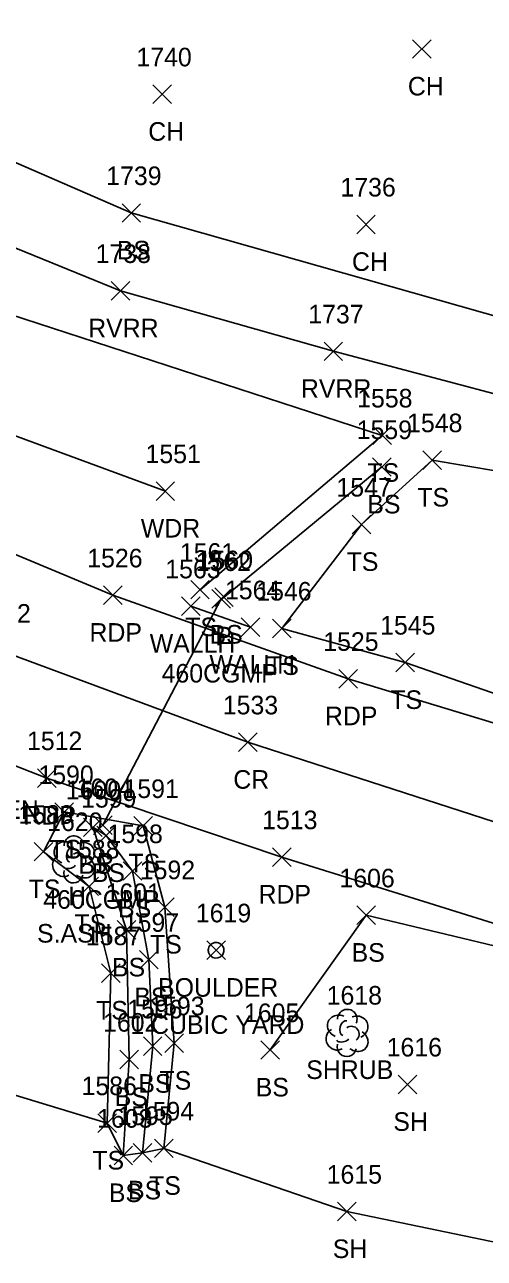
# Model space of a CAD drawing. Extents: x 1616726 to 1619875, y 273782 to 276557.
# Drawn here: x 1616834 to 1616883.5, y 276165.6 to 276298.3 of the extents above; entities that cross this region are included whole.
import ezdxf

# ---------------------------------------------------------------- set-up
doc = ezdxf.new("R2010")
doc.units = 0
for name, color, linetype in [('D_A', 7, 'Continuous'), ('D_C', 7, 'Continuous'), ('D_I', 7, 'Continuous'), ('D_TIC', 7, 'Continuous'), ('DCP', 7, 'Continuous'), ('DHW', 7, 'Continuous'), ('L_A', 7, 'Continuous'), ('L_C', 7, 'Continuous'), ('L_I', 7, 'Continuous'), ('L_TIC', 7, 'Continuous'), ('LAWA', 7, 'Continuous'), ('LAWE', 7, 'Continuous'), ('LELB', 7, 'Continuous'), ('Level 45', 7, 'Continuous'), ('LSH', 7, 'Continuous'), ('LSOGP', 7, 'Continuous'), ('LTD', 7, 'Continuous'), ('P_A', 7, 'Continuous'), ('P_I', 7, 'Continuous'), ('P_TIC', 7, 'Continuous'), ('PET', 7, 'Continuous'), ('PRC', 7, 'Continuous')]:
    doc.layers.add(name, color=color, linetype=linetype)

msp = doc.modelspace()

# ---------------------------------------------------------------- linework, layer by layer
at = {"layer": 'D_TIC'}
for points in [[(1616850.89, 276234.79), (1616852.89, 276236.79)], [(1616852.89, 276234.79), (1616850.89, 276236.79)], [(1616854.16, 276235.58), (1616856.16, 276237.58)], [(1616856.16, 276235.58), (1616854.16, 276237.58)], [(1616857.31, 276232.54), (1616859.31, 276234.54)], [(1616859.31, 276232.54), (1616857.31, 276234.54)], [(1616841.43, 276211.25), (1616843.43, 276213.25)], [(1616843.43, 276211.25), (1616841.43, 276213.25)]]:
    msp.add_lwpolyline(points, dxfattribs=at)
at = {"layer": 'DCP'}
msp.add_lwpolyline([(1616855.16, 276236.58), (1616842.43, 276212.25)], dxfattribs=at)
at = {"layer": 'DHW'}
msp.add_lwpolyline([(1616851.89, 276235.79), (1616858.31, 276233.54)], dxfattribs=at)
at = {"layer": 'L_TIC'}
for points in [[(1616875.75, 276294.73), (1616877.75, 276296.73)], [(1616877.75, 276294.73), (1616875.75, 276296.73)], [(1616847.83, 276289.86), (1616849.83, 276291.86)], [(1616849.83, 276289.86), (1616847.83, 276291.86)], [(1616844.5, 276277.09), (1616846.5, 276279.09)], [(1616846.5, 276277.09), (1616844.5, 276279.09)], [(1616869.74, 276275.86), (1616871.74, 276277.86)], [(1616871.74, 276275.86), (1616869.74, 276277.86)], [(1616843.35, 276268.71), (1616845.35, 276270.71)], [(1616845.35, 276268.71), (1616843.35, 276270.71)], [(1616866.23, 276262.21), (1616868.23, 276264.21)], [(1616868.23, 276262.21), (1616866.23, 276264.21)], [(1616871.48, 276253.17), (1616873.48, 276255.17)], [(1616873.48, 276253.17), (1616871.48, 276255.17)], [(1616876.85, 276250.51), (1616878.85, 276252.51)], [(1616878.85, 276250.51), (1616876.85, 276252.51)], [(1616871.44, 276249.77), (1616873.44, 276251.77)], [(1616873.44, 276249.77), (1616871.44, 276251.77)], [(1616848.16, 276247.18), (1616850.16, 276249.18)], [(1616850.16, 276247.18), (1616848.16, 276249.18)], [(1616869.25, 276243.59), (1616871.25, 276245.59)], [(1616871.25, 276243.59), (1616869.25, 276245.59)], [(1616851.89, 276236.57), (1616853.89, 276238.57)], [(1616853.89, 276236.57), (1616851.89, 276238.57)], [(1616854.47, 276235.77), (1616856.47, 276237.77)], [(1616856.47, 276235.77), (1616854.47, 276237.77)], [(1616860.69, 276232.4), (1616862.69, 276234.4)], [(1616862.69, 276232.4), (1616860.69, 276234.4)], [(1616873.95, 276228.74), (1616875.95, 276230.74)], [(1616875.95, 276228.74), (1616873.95, 276230.74)], [(1616837.28, 276212.66), (1616839.28, 276214.66)], [(1616839.28, 276212.66), (1616837.28, 276214.66)], [(1616840.37, 276211.01), (1616842.37, 276213.01)], [(1616842.37, 276211.01), (1616840.37, 276213.01)], [(1616845.78, 276211.16), (1616847.78, 276213.16)], [(1616847.78, 276211.16), (1616845.78, 276213.16)], [(1616841.8, 276210.13), (1616843.8, 276212.13)], [(1616843.8, 276210.13), (1616841.8, 276212.13)], [(1616835.05, 276208.39), (1616837.05, 276210.39)], [(1616837.05, 276208.39), (1616835.05, 276210.39)], [(1616844.63, 276206.31), (1616846.63, 276208.31)], [(1616846.63, 276206.31), (1616844.63, 276208.31)], [(1616839.98, 276204.66), (1616841.98, 276206.66)], [(1616841.98, 276204.66), (1616839.98, 276206.66)], [(1616848.1, 276202.43), (1616850.1, 276204.43)], [(1616850.1, 276202.43), (1616848.1, 276204.43)], [(1616869.75, 276201.55), (1616871.75, 276203.55)], [(1616871.75, 276201.55), (1616869.75, 276203.55)], [(1616843.98, 276199.97), (1616845.98, 276201.97)], [(1616845.98, 276199.97), (1616843.98, 276201.97)], [(1616853.62, 276197.79), (1616855.62, 276199.79)], [(1616855.62, 276197.79), (1616853.62, 276199.79)], [(1616846.38, 276196.77), (1616848.38, 276198.77)], [(1616848.38, 276196.77), (1616846.38, 276198.77)], [(1616842.3, 276195.33), (1616844.3, 276197.33)], [(1616844.3, 276195.33), (1616842.3, 276197.33)], [(1616846.8, 276187.46), (1616848.8, 276189.46)], [(1616848.8, 276187.46), (1616846.8, 276189.46)], [(1616849.12, 276187.79), (1616851.12, 276189.79)], [(1616851.12, 276187.79), (1616849.12, 276189.79)], [(1616859.43, 276187.06), (1616861.43, 276189.06)], [(1616861.43, 276187.06), (1616859.43, 276189.06)], [(1616844.27, 276186.03), (1616846.27, 276188.03)], [(1616846.27, 276186.03), (1616844.27, 276188.03)], [(1616874.19, 276183.36), (1616876.19, 276185.36)], [(1616876.19, 276183.36), (1616874.19, 276185.36)], [(1616841.9, 276179.2), (1616843.9, 276181.2)], [(1616843.9, 276179.2), (1616841.9, 276181.2)], [(1616848.01, 276176.48), (1616850.01, 276178.48)], [(1616850.01, 276176.48), (1616848.01, 276178.48)], [(1616843.64, 276175.7), (1616845.64, 276177.7)], [(1616845.64, 276175.7), (1616843.64, 276177.7)], [(1616845.71, 276175.99), (1616847.71, 276177.99)], [(1616847.71, 276175.99), (1616845.71, 276177.99)], [(1616867.68, 276169.68), (1616869.68, 276171.68)], [(1616869.68, 276169.68), (1616867.68, 276171.68)]]:
    msp.add_lwpolyline(points, dxfattribs=at)
at = {"layer": 'LAWA'}
msp.add_lwpolyline([(1616849.16, 276248.18), (1616818.87, 276259.31), (1616781.79, 276275.58)], dxfattribs=at)
at = {"layer": 'LAWE'}
msp.add_lwpolyline([(1617025.7, 276233.23), (1617015.62, 276235.97), (1617001.8, 276236.48), (1616993.71, 276237.76), (1616982.58, 276237.2), (1616969.98, 276238.82), (1616958.41, 276240.14), (1616941.63, 276245.84), (1616918.28, 276250.86), (1616897.52, 276255.18), (1616867.23, 276263.21), (1616844.35, 276269.71), (1616814.42, 276281.91), (1616791.45, 276293.2)], dxfattribs=at)
at = {"layer": 'LELB'}
for points in [[(1617180.33, 276288.33), (1617161.43, 276281.85), (1617137.1, 276278.45), (1617120.41, 276268.03), (1617108.3, 276262.95), (1617094.24, 276258.02), (1617079.48, 276248.1), (1617068.22, 276247.78), (1617049.15, 276245.5), (1617035.06, 276240.81), (1617026.01, 276236.23), (1617014.97, 276241.9), (1616972.47, 276247.82), (1616960.61, 276245.77), (1616944.03, 276250.47), (1616920.65, 276257.27), (1616898.69, 276263.02), (1616845.5, 276278.09), (1616816.83, 276290.56), (1616792.38, 276296.23)], [(1616787.97, 276286.47), (1616805.45, 276276.63), (1616830.82, 276267.71), (1616872.48, 276254.17), (1616852.89, 276237.57)], [(1616930.41, 276218.6), (1616913.38, 276221.93), (1616895.08, 276222.74), (1616874.95, 276229.74), (1616861.69, 276233.4), (1616870.25, 276244.59), (1616877.85, 276251.51), (1616899.15, 276247.91), (1616918.01, 276240.69)], [(1616872.44, 276250.77), (1616855.47, 276236.77)], [(1616842.9, 276180.2), (1616843.3, 276196.33), (1616840.98, 276205.66), (1616836.05, 276209.39), (1616838.28, 276213.66), (1616846.78, 276212.16), (1616849.1, 276203.43), (1616850.12, 276188.79), (1616849.01, 276177.48)], [(1616846.71, 276176.99), (1616847.8, 276188.46), (1616847.38, 276197.77), (1616845.63, 276207.31), (1616842.8, 276211.13), (1616841.37, 276212.01), (1616844.98, 276200.97), (1616845.27, 276187.03), (1616844.64, 276176.7)], [(1616860.43, 276188.06), (1616870.75, 276202.55), (1616889.75, 276198.01), (1616902.37, 276195.47)]]:
    msp.add_lwpolyline(points, dxfattribs=at)
at = {"layer": 'Level 45'}
msp.add_lwpolyline([(1616853.78, 276198.83), (1616853.78, 276198.75), (1616853.79, 276198.65), (1616853.81, 276198.56), (1616853.84, 276198.49), (1616853.87, 276198.42), (1616853.89, 276198.36), (1616853.93, 276198.3), (1616853.99, 276198.23), (1616854.04, 276198.18), (1616854.12, 276198.11), (1616854.27, 276198.02), (1616854.4, 276197.97), (1616854.58, 276197.94), (1616854.79, 276197.96), (1616854.92, 276198), (1616855.03, 276198.05), (1616855.13, 276198.11), (1616855.21, 276198.18), (1616855.26, 276198.24), (1616855.33, 276198.32), (1616855.39, 276198.44), (1616855.43, 276198.54), (1616855.46, 276198.67), (1616855.46, 276198.82), (1616855.44, 276198.99), (1616855.41, 276199.09), (1616855.36, 276199.19), (1616855.28, 276199.32), (1616855.18, 276199.42), (1616855.01, 276199.53), (1616854.87, 276199.59), (1616854.72, 276199.62), (1616854.6, 276199.63), (1616854.46, 276199.62), (1616854.29, 276199.56), (1616854.19, 276199.51), (1616854.07, 276199.42), (1616853.94, 276199.29), (1616853.89, 276199.2), (1616853.85, 276199.11), (1616853.8, 276198.99), (1616853.79, 276198.93)], close=True, dxfattribs=at)
at = {"layer": 'LSH'}
msp.add_line((1616868.68, 276189.94), (1616868.68, 276189.94), dxfattribs=at)
msp.add_line((1616868.68, 276189.94), (1616868.68, 276189.94), dxfattribs=at)
msp.add_arc((1616868.73, 276191.38), 1.05, 335.5272, 180.9563, dxfattribs=at)
for centre, major_axis, ratio, start_param, end_param in [((1616867.89, 276190.61), (1.21, -0.51), 0.895232, 1.570796, 4.712389), ((1616869.72, 276190.53), (-1.14, -0.48), 0.949671, 1.570796, 4.712389), ((1616867.6, 276189.23), (0.58, -1.04), 0.959034, 3.141593, 6.283185), ((1616868.47, 276190.4), (-0.208, -0.792), 0.645439, 3.141593, 6.283185), ((1616869.18, 276189.78), (-0.5, 0.667), 0.989748, 3.141593, 6.283185), ((1616868.22, 276189.19), (-0.625, -0.083), 0.423636, 0, 3.141593), ((1616869.68, 276189.11), (-1.09, 0.79), 0.841452, 1.570796, 4.712389), ((1616868.68, 276188.44), (0.26, 1.06), 0.942809, 1.570796, 4.712389)]:
    msp.add_ellipse(centre, major_axis=major_axis, ratio=ratio, start_param=start_param, end_param=end_param, dxfattribs=at)
at = {"layer": 'LSOGP'}
msp.add_lwpolyline([(1616793.68, 276308.95), (1616792.38, 276296.23), (1616791.45, 276293.2), (1616787.97, 276286.47), (1616782.93, 276276.29), (1616781.79, 276275.58), (1616777.93, 276266.16), (1616773.7, 276256.44), (1616769.24, 276246.91), (1616756.89, 276246.26), (1616747.56, 276224.4), (1616766.56, 276216.64), (1616771.16, 276212.03), (1616782.84, 276206.49), (1616798.63, 276193.86), (1616823.2, 276186.17), (1616842.9, 276180.2), (1616844.64, 276176.7), (1616846.71, 276176.99), (1616849.01, 276177.48), (1616868.68, 276170.68), (1616889.93, 276166.26)], dxfattribs=at)
at = {"layer": 'LTD'}
msp.add_line((1616839.28, 276208.61), (1616839.28, 276208.61), dxfattribs=at)
msp.add_line((1616839.28, 276208.61), (1616839.28, 276208.61), dxfattribs=at)
msp.add_arc((1616839.32, 276210.04), 1.05, 335.5272, 180.9563, dxfattribs=at)
for centre, major_axis, ratio, start_param, end_param in [((1616838.49, 276209.27), (1.21, -0.51), 0.895232, 1.570796, 4.712389), ((1616840.32, 276209.19), (-1.14, -0.48), 0.949671, 1.570796, 4.712389), ((1616838.19, 276207.9), (0.58, -1.04), 0.959034, 3.141593, 6.283185), ((1616839.07, 276209.07), (-0.208, -0.792), 0.645439, 3.141593, 6.283185), ((1616839.78, 276208.44), (-0.5, 0.667), 0.989748, 3.141593, 6.283185), ((1616840.28, 276207.77), (-1.09, 0.79), 0.841452, 1.570796, 4.712389), ((1616839.28, 276207.11), (0.26, 1.06), 0.942809, 1.570796, 4.712389), ((1616838.82, 276207.86), (-0.625, -0.083), 0.423636, 0, 3.141593)]:
    msp.add_ellipse(centre, major_axis=major_axis, ratio=ratio, start_param=start_param, end_param=end_param, dxfattribs=at)
at = {"layer": 'P_TIC'}
for points in [[(1616842.51, 276235.97), (1616844.51, 276237.97)], [(1616844.51, 276235.97), (1616842.51, 276237.97)], [(1616867.83, 276226.99), (1616869.83, 276228.99)], [(1616869.83, 276226.99), (1616867.83, 276228.99)], [(1616857.04, 276220.16), (1616859.04, 276222.16)], [(1616859.04, 276220.16), (1616857.04, 276222.16)], [(1616835.41, 276216.31), (1616837.41, 276218.31)], [(1616837.41, 276216.31), (1616835.41, 276218.31)], [(1616860.69, 276207.81), (1616862.69, 276209.81)], [(1616862.69, 276207.81), (1616860.69, 276209.81)]]:
    msp.add_lwpolyline(points, dxfattribs=at)
at = {"layer": 'PET'}
for points in [[(1616988.41, 276201.28), (1616954.9, 276207.04), (1616922.49, 276213.04), (1616897.19, 276219.39), (1616868.83, 276227.99), (1616843.51, 276236.97), (1616821.5, 276246.17), (1616797.48, 276256.89), (1616777.93, 276266.16)], [(1616769.24, 276246.91), (1616790.9, 276236.62), (1616808.6, 276228.19), (1616836.41, 276217.31), (1616861.69, 276208.81), (1616891.18, 276199.57), (1616916.28, 276193.27), (1616944.97, 276187.68), (1616979.27, 276181.76), (1617009.13, 276177.18), (1617040.1, 276173.73), (1617058.02, 276171.48)]]:
    msp.add_lwpolyline(points, dxfattribs=at)
at = {"layer": 'PRC'}
msp.add_lwpolyline([(1616773.7, 276256.44), (1616798, 276244.91), (1616831.43, 276231.02), (1616858.04, 276221.16), (1616889.3, 276211.07), (1616917.92, 276203.82), (1616952.65, 276196.97), (1616987.1, 276190.69)], dxfattribs=at)

# ---------------------------------------------------------------- texts
at = {"layer": 'D_A'}
for s, p in [('WALLH', (1616847.48, 276230.79)), ('P', (1616854.54, 276231.58)), ('WALLH', (1616853.9, 276228.54)), ('P', (1616841.81, 276207.25))]:
    msp.add_text(s, height=2, dxfattribs=at).set_placement(p)
at = {"layer": 'D_C'}
for p in [(1616848.76, 276227.58), (1616836.03, 276203.25)]:
    msp.add_text('460CGMP', height=2, dxfattribs=at).set_placement(p)
at = {"layer": 'D_I'}
for s, p in [('1563', (1616849.15, 276238.79)), ('1562', (1616852.42, 276239.58)), ('1564', (1616855.57, 276236.54)), ('1604', (1616839.61, 276215.25))]:
    msp.add_text(s, height=2, dxfattribs=at).set_placement(p)
at = {"layer": 'L_A'}
for s, p in [('CH', (1616875.24, 276290.73)), ('CH', (1616847.32, 276285.86)), ('BS', (1616843.94, 276273.09)), ('CH', (1616869.23, 276271.86)), ('RVRR', (1616840.86, 276264.71)), ('RVRR', (1616863.74, 276258.21)), ('TS', (1616870.89, 276249.17)), ('TS', (1616876.26, 276246.51)), ('BS', (1616870.88, 276245.77)), ('WDR', (1616846.52, 276243.18)), ('TS', (1616868.66, 276239.59)), ('TS', (1616851.3, 276232.57)), ('BS', (1616853.91, 276231.77)), ('TS', (1616860.1, 276228.4)), ('TS', (1616873.36, 276224.74)), ('GARDEN', (1616824.11, 276212.92)), ('TS', (1616836.69, 276208.66)), ('BS', (1616839.81, 276207.01)), ('TS', (1616845.19, 276207.16)), ('BS', (1616841.24, 276206.13)), ('TS', (1616834.46, 276204.39)), ('H', (1616838.71, 276203.61)), ('BS', (1616844.07, 276202.31)), ('TS', (1616839.39, 276200.66)), ('TS', (1616847.51, 276198.43)), ('BS', (1616869.19, 276197.55)), ('BS', (1616843.42, 276195.97)), ('BOULDER', (1616848.38, 276193.79)), ('BS', (1616845.82, 276192.77)), ('TS', (1616841.71, 276191.33)), ('SHRUB', (1616864.31, 276184.94)), ('BS', (1616846.25, 276183.46)), ('TS', (1616848.53, 276183.79)), ('BS', (1616858.88, 276183.06)), ('BS', (1616843.72, 276182.03)), ('SH', (1616873.68, 276179.36)), ('TS', (1616841.31, 276175.2)), ('TS', (1616847.41, 276172.48)), ('BS', (1616843.08, 276171.7)), ('BS', (1616845.15, 276171.99)), ('SH', (1616867.17, 276165.68))]:
    msp.add_text(s, height=2, dxfattribs=at).set_placement(p)
at = {"layer": 'L_C'}
for s, p in [('S.ASH', (1616835.36, 276199.61)), ('1 CUBIC YARD', (1616845.39, 276189.79))]:
    msp.add_text(s, height=2, dxfattribs=at).set_placement(p)
at = {"layer": 'L_I'}
for s, p in [('1740', (1616846.05, 276293.86)), ('1739', (1616842.8, 276281.09)), ('1736', (1616867.99, 276279.86)), ('1738', (1616841.66, 276272.71)), ('1737', (1616864.53, 276266.21)), ('1558', (1616869.79, 276257.17)), ('1548', (1616875.16, 276254.51)), ('1559', (1616869.74, 276253.77)), ('1551', (1616847.03, 276251.18)), ('1547', (1616867.56, 276247.59)), ('1561', (1616850.72, 276240.57)), ('1560', (1616852.64, 276239.77)), ('1546', (1616858.94, 276236.4)), ('1545', (1616872.26, 276232.74)), ('1590', (1616835.51, 276216.66)), ('1600', (1616838.46, 276215.01)), ('1591', (1616844.66, 276215.16)), ('1599', (1616840.1, 276214.13)), ('1589', (1616833.35, 276212.39)), ('1620', (1616836.45, 276211.61)), ('1598', (1616842.94, 276210.31)), ('1588', (1616838.28, 276208.66)), ('1592', (1616846.41, 276206.43)), ('1606', (1616867.88, 276205.55)), ('1601', (1616842.73, 276203.97)), ('1619', (1616852.44, 276201.79)), ('1597', (1616844.69, 276200.77)), ('1587', (1616840.61, 276199.33)), ('1618', (1616866.51, 276192.94)), ('1596', (1616845.06, 276191.46)), ('1593', (1616847.43, 276191.79)), ('1605', (1616857.62, 276191.06)), ('1602', (1616842.46, 276190.03)), ('1616', (1616872.96, 276187.36)), ('1586', (1616840.15, 276183.2)), ('1594', (1616846.31, 276180.48)), ('1603', (1616841.82, 276179.7)), ('1595', (1616844.02, 276179.99)), ('1615', (1616866.51, 276173.68))]:
    msp.add_text(s, height=2, dxfattribs=at).set_placement(p)
at = {"layer": 'P_A'}
for s, p in [('RDP', (1616841, 276231.97)), ('RDP', (1616866.32, 276222.99)), ('CR', (1616856.47, 276216.16)), ('RDP', (1616833.9, 276212.31)), ('RDP', (1616859.18, 276203.81))]:
    msp.add_text(s, height=2, dxfattribs=at).set_placement(p)
at = {"layer": 'P_I'}
for s, p in [('1526', (1616840.76, 276239.97)), ('1532', (1616828.74, 276234.02)), ('1525', (1616866.14, 276230.99)), ('1533', (1616855.34, 276224.16)), ('1512', (1616834.28, 276220.31)), ('1513', (1616859.57, 276211.81))]:
    msp.add_text(s, height=2, dxfattribs=at).set_placement(p)

doc.saveas('drawing.dxf')
